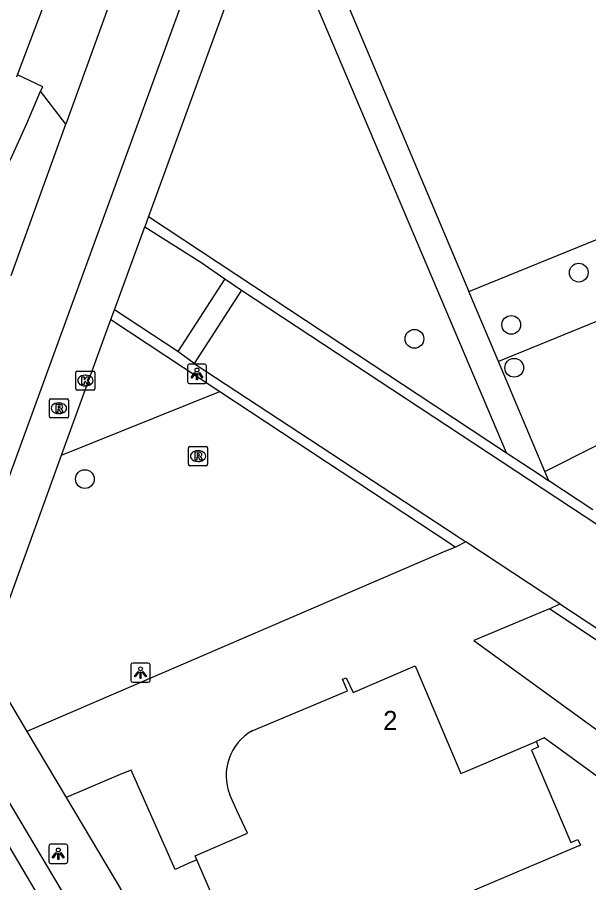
# Model space of a CAD drawing. Extents: x 156664 to 157568, y 383571 to 384421.
# Drawn here: x 156680.16 to 156709.98, y 383856.29 to 383901.43 of the extents above; entities that cross this region are included whole.
import ezdxf

# ---------------------------------------------------------------- set-up
doc = ezdxf.new("R2010")
doc.units = 0
for name, color, linetype in [('IMGEO_Boom', 7, 'Continuous'), ('IMGEO_Fietspad_open', 7, 'Continuous'), ('IMGEO_Groenvoorziening', 7, 'Continuous'), ('IMGEO_Kolk', 7, 'Continuous'), ('IMGEO_Lichtpunt', 7, 'Continuous'), ('IMGEO_OVBaan_gesloten', 7, 'Continuous'), ('IMGEO_Pand', 7, 'Continuous'), ('IMGEO_Pand_nummerreeks', 7, 'Continuous'), ('IMGEO_Rijbaan_lokaal_halfverhard', 7, 'Continuous'), ('IMGEO_Rijbaan_lokaal_open', 7, 'Continuous'), ('IMGEO_Rioolput', 7, 'Continuous'), ('IMGEO_Voetpad_open', 7, 'Continuous')]:
    doc.layers.add(name, color=color, linetype=linetype)

msp = doc.modelspace()

# ---------------------------------------------------------------- linework, layer by layer
at = {"layer": 'IMGEO_Boom'}
for centre in [(156709.463, 383888.111), (156705.943, 383885.387), (156700.888, 383884.658), (156706.096, 383883.15), (156683.69, 383877.346)]:
    msp.add_circle(centre, 0.489, dxfattribs=at)
at = {"layer": 'IMGEO_Fietspad_open'}
for points in [[(156833.031, 384293.583), (156831.476, 384295.664), (156797.885, 384202.753), (156781.915, 384158.669), (156778.633, 384149.604), (156765.945, 384114.759), (156745.635, 384058.756), (156737.507, 384036.302), (156716.373, 383978.18), (156709.217, 383958.49), (156701.659, 383937.694), (156690.408, 383906.735), (156677.045, 383870.138), (156675.34, 383865.46)], [(156685.19, 383902.73), (156682.699, 383895.852)]]:
    msp.add_lwpolyline(points, dxfattribs=at)
at = {"layer": 'IMGEO_Groenvoorziening'}
for points in [[(156703.732, 383887.135), (156723.792, 383895.282), (156723.972, 383894.805)], [(156707.702, 383877.745), (156721.247, 383884.56), (156720.319, 383889.614), (156705.282, 383883.469)], [(156682.477, 383878.585), (156690.731, 383881.92)]]:
    msp.add_lwpolyline(points, dxfattribs=at)
at = {"layer": 'IMGEO_Kolk'}
for p, q in [((156683.218, 383882.054), (156683.218, 383882.906)), ((156683.293, 383882.98), (156684.145, 383882.98)), ((156683.706, 383882.76), (156683.731, 383882.76)), ((156684.219, 383882.906), (156684.219, 383882.054)), ((156683.729, 383882.2), (156683.704, 383882.2)), ((156684.145, 383881.98), (156683.293, 383881.98))]:
    msp.add_line(p, q, dxfattribs=at)
for points in [[(156683.218, 383882.054), (156683.218, 383882.906)], [(156683.293, 383882.98), (156684.145, 383882.98)], [(156683.539, 383882.68), (156683.662, 383882.68), (156683.662, 383882.529), (156683.792, 383882.68), (156683.956, 383882.68), (156683.81, 383882.529), (156683.963, 383882.28), (156683.811, 383882.28), (156683.726, 383882.444), (156683.662, 383882.377), (156683.662, 383882.28), (156683.539, 383882.28), (156683.539, 383882.68)], [(156684.219, 383882.906), (156684.219, 383882.054)], [(156684.145, 383881.98), (156683.293, 383881.98)]]:
    msp.add_lwpolyline(points, dxfattribs=at)
for centre, start, end in [((156683.295, 383882.904), 91.552, 178.448), ((156683.295, 383882.904), 91.552, 178.448), ((156684.143, 383882.904), 1.552, 88.448), ((156684.143, 383882.904), 1.552, 88.448), ((156683.295, 383882.056), 181.552, 268.448), ((156683.295, 383882.056), 181.552, 268.448), ((156684.143, 383882.056), 271.552, 358.448), ((156684.143, 383882.056), 271.552, 358.448)]:
    msp.add_arc(centre, 0.0765, start, end, dxfattribs=at)
for centre, major_axis, ratio, start_param, end_param in [((156683.705, 383882.48), (-0.387, 0.002), 0.722429, 4.712389, 7.853982), ((156683.73, 383882.48), (-0.39, 0.002), 0.717154, 1.570796, 4.712389)]:
    msp.add_ellipse(centre, major_axis=major_axis, ratio=ratio, start_param=start_param, end_param=end_param, dxfattribs=at)
at = {"layer": 'IMGEO_Lichtpunt'}
for p, q in [((156689.044, 383883.235), (156689.044, 383882.428)), ((156689.044, 383883.235), (156689.044, 383882.428)), ((156689.946, 383883.33), (156689.138, 383883.33)), ((156689.946, 383883.33), (156689.138, 383883.33)), ((156690.04, 383882.428), (156690.04, 383883.235)), ((156690.04, 383882.428), (156690.04, 383883.235)), ((156689.138, 383882.334), (156689.946, 383882.334)), ((156689.138, 383882.334), (156689.946, 383882.334)), ((156686.996, 383867.746), (156686.188, 383867.746)), ((156686.996, 383867.746), (156686.188, 383867.746)), ((156686.094, 383867.651), (156686.094, 383866.844)), ((156686.094, 383867.651), (156686.094, 383866.844)), ((156687.09, 383866.844), (156687.09, 383867.651)), ((156687.09, 383866.844), (156687.09, 383867.651)), ((156686.188, 383866.75), (156686.996, 383866.75)), ((156686.188, 383866.75), (156686.996, 383866.75)), ((156681.804, 383858.205), (156681.804, 383857.398)), ((156681.804, 383858.205), (156681.804, 383857.398)), ((156682.706, 383858.3), (156681.898, 383858.3)), ((156682.706, 383858.3), (156681.898, 383858.3)), ((156682.8, 383857.398), (156682.8, 383858.205)), ((156682.8, 383857.398), (156682.8, 383858.205)), ((156681.898, 383857.304), (156682.706, 383857.304)), ((156681.898, 383857.304), (156682.706, 383857.304))]:
    msp.add_line(p, q, dxfattribs=at)
for points in [[(156689.418, 383882.899), (156689.457, 383882.871), (156689.269, 383882.609), (156689.231, 383882.636), (156689.418, 383882.899)], [(156689.52, 383882.851), (156689.567, 383882.851), (156689.567, 383882.529), (156689.52, 383882.529), (156689.52, 383882.851)], [(156689.63, 383882.871), (156689.668, 383882.898), (156689.855, 383882.636), (156689.816, 383882.608), (156689.63, 383882.871)], [(156686.468, 383867.315), (156686.507, 383867.287), (156686.319, 383867.025), (156686.281, 383867.052), (156686.468, 383867.315)], [(156686.57, 383867.267), (156686.617, 383867.267), (156686.617, 383866.945), (156686.57, 383866.945), (156686.57, 383867.267)], [(156686.68, 383867.287), (156686.718, 383867.314), (156686.905, 383867.052), (156686.866, 383867.024), (156686.68, 383867.287)], [(156682.178, 383857.869), (156682.217, 383857.841), (156682.029, 383857.579), (156681.991, 383857.606), (156682.178, 383857.869)], [(156682.28, 383857.821), (156682.327, 383857.821), (156682.327, 383857.499), (156682.28, 383857.499), (156682.28, 383857.821)], [(156682.39, 383857.841), (156682.428, 383857.868), (156682.615, 383857.606), (156682.576, 383857.578), (156682.39, 383857.841)]]:
    msp.add_lwpolyline(points, dxfattribs=at)
for centre in [(156689.543, 383883.033), (156686.593, 383867.449), (156682.303, 383858.003)]:
    msp.add_circle(centre, 0.0994, dxfattribs=at)
for centre, start, end in [((156689.138, 383883.235), 90, 180), ((156689.138, 383883.235), 90, 180), ((156689.946, 383883.235), 0, 90), ((156689.946, 383883.235), 0, 90), ((156689.138, 383882.428), 180, 270), ((156689.138, 383882.428), 180, 270), ((156689.946, 383882.428), 270, 0), ((156689.946, 383882.428), 270, 360), ((156686.188, 383867.651), 90, 180), ((156686.188, 383867.651), 90, 180), ((156686.996, 383867.651), 0, 90), ((156686.996, 383867.651), 0, 90), ((156686.188, 383866.844), 180, 270), ((156686.188, 383866.844), 180, 270), ((156686.996, 383866.844), 270, 0), ((156686.996, 383866.844), 270, 360), ((156681.898, 383858.205), 90, 180), ((156681.898, 383858.205), 90, 180), ((156682.706, 383858.205), 0, 90), ((156682.706, 383858.205), 0, 90), ((156681.898, 383857.398), 180, 270), ((156681.898, 383857.398), 180, 270), ((156682.706, 383857.398), 270, 0), ((156682.706, 383857.398), 270, 360)]:
    msp.add_arc(centre, 0.0946, start, end, dxfattribs=at)
at = {"layer": 'IMGEO_OVBaan_gesloten'}
msp.add_lwpolyline([(156692.043, 383837.395), (156678.244, 383860.711)], dxfattribs=at)
at = {"layer": 'IMGEO_Pand'}
for points in [[(156692.428, 383864.216), (156697.403, 383866.292), (156697.143, 383866.907), (156697.33, 383866.987), (156697.694, 383866.219), (156700.923, 383867.6), (156703.32, 383861.991), (156703.808, 383862.199), (156707.237, 383863.666)], [(156707.237, 383863.666), (156707.363, 383863.372), (156706.995, 383863.214), (156709.056, 383858.397), (156709.424, 383858.554), (156709.549, 383858.26), (156704.398, 383856.067), (156692.389, 383850.886), (156689.54, 383857.489)], [(156689.54, 383857.489), (156689.45, 383857.699), (156692.177, 383858.875), (156691.614, 383860.059), (156691.257, 383860.885)]]:
    msp.add_lwpolyline(points, dxfattribs=at)
msp.add_arc((156693.739, 383861.884), 2.676, 119.3437, 201.9185, dxfattribs=at)
at = {"layer": 'IMGEO_Rijbaan_lokaal_halfverhard'}
for points in [[(156687.008, 383891.046), (156686.812, 383890.508)], [(156687.008, 383891.046), (156697.05, 383884.421), (156701.09, 383881.756), (156705.692, 383878.72)], [(156685.05, 383885.669), (156685.231, 383886.168)], [(156685.05, 383885.669), (156690.731, 383881.92)], [(156690.731, 383881.92), (156702.732, 383874), (156703.031, 383873.802)], [(156705.692, 383878.72), (156707.4, 383877.593), (156707.907, 383877.258)], [(156710.197, 383875.747), (156707.907, 383877.258)], [(156703.578, 383874.065), (156703.031, 383873.802)], [(156707.93, 383870.575), (156708.48, 383870.841)], [(156724.088, 383859.825), (156708.317, 383870.317), (156707.93, 383870.575)]]:
    msp.add_lwpolyline(points, dxfattribs=at)
at = {"layer": 'IMGEO_Rijbaan_lokaal_open'}
for points in [[(156680.183, 383898.426), (156682.204, 383903.825)], [(156680.146, 383898.326), (156680.183, 383898.426)], [(156681.368, 383897.568), (156681.498, 383897.809), (156680.183, 383898.426)], [(156676.643, 383888.338), (156677.506, 383889.734), (156678.327, 383891.155), (156679.104, 383892.6), (156679.914, 383894.23), (156680.669, 383895.887), (156681.368, 383897.568)], [(156682.699, 383895.852), (156681.368, 383897.568)], [(156679.844, 383887.968), (156682.699, 383895.852)], [(156685.231, 383886.168), (156686.812, 383890.508)], [(156686.812, 383890.508), (156689.735, 383888.649), (156690.998, 383887.79)], [(156690.998, 383887.79), (156688.55, 383883.993)], [(156690.998, 383887.79), (156691.868, 383887.197)], [(156691.868, 383887.197), (156689.389, 383883.375)], [(156691.868, 383887.197), (156726.961, 383864.085)], [(156688.55, 383883.993), (156688.542, 383883.999), (156685.231, 383886.168)], [(156689.389, 383883.375), (156688.55, 383883.993)], [(156689.389, 383883.375), (156703.099, 383874.38), (156703.578, 383874.065)], [(156708.48, 383870.841), (156703.578, 383874.065)], [(156708.48, 383870.841), (156724.436, 383860.345)]]:
    msp.add_lwpolyline(points, dxfattribs=at)
at = {"layer": 'IMGEO_Rioolput'}
for p, q in [((156681.837, 383880.61), (156681.837, 383881.462)), ((156681.912, 383881.536), (156682.764, 383881.536)), ((156682.325, 383881.316), (156682.35, 383881.316)), ((156682.838, 383881.462), (156682.838, 383880.61)), ((156682.348, 383880.756), (156682.323, 383880.756)), ((156682.764, 383880.536), (156681.912, 383880.536)), ((156689.097, 383878.114), (156689.097, 383878.966)), ((156689.172, 383879.04), (156690.024, 383879.04)), ((156690.098, 383878.966), (156690.098, 383878.114)), ((156689.585, 383878.82), (156689.61, 383878.82)), ((156689.608, 383878.26), (156689.583, 383878.26)), ((156690.024, 383878.04), (156689.172, 383878.04))]:
    msp.add_line(p, q, dxfattribs=at)
for points in [[(156681.837, 383880.61), (156681.837, 383881.462)], [(156681.912, 383881.536), (156682.764, 383881.536)], [(156682.426, 383881.234), (156682.174, 383881.236), (156682.174, 383880.836)], [(156682.838, 383881.462), (156682.838, 383880.61)], [(156682.174, 383880.836), (156682.298, 383880.836), (156682.298, 383880.998), (156682.309, 383880.998)], [(156682.352, 383881.155), (156682.298, 383881.155), (156682.298, 383881.074)], [(156682.298, 383881.074), (156682.35, 383881.074)], [(156682.356, 383880.969), (156682.427, 383880.836), (156682.567, 383880.836), (156682.502, 383880.962)], [(156682.764, 383880.536), (156681.912, 383880.536)], [(156689.097, 383878.114), (156689.097, 383878.966)], [(156689.172, 383879.04), (156690.024, 383879.04)], [(156690.098, 383878.966), (156690.098, 383878.114)], [(156689.686, 383878.738), (156689.434, 383878.74), (156689.434, 383878.34)], [(156689.434, 383878.34), (156689.558, 383878.34), (156689.558, 383878.502), (156689.569, 383878.502)], [(156689.612, 383878.659), (156689.558, 383878.659), (156689.558, 383878.578)], [(156689.558, 383878.578), (156689.61, 383878.578)], [(156689.616, 383878.473), (156689.687, 383878.34), (156689.827, 383878.34), (156689.762, 383878.466)], [(156690.024, 383878.04), (156689.172, 383878.04)]]:
    msp.add_lwpolyline(points, dxfattribs=at)
for centre, radius, start, end in [((156681.914, 383881.46), 0.0765, 91.552, 178.448), ((156681.914, 383881.46), 0.0765, 91.552, 178.448), ((156682.425, 383881.124), 0.109, 350.3612, 89.416), ((156682.762, 383881.46), 0.0765, 1.552, 88.448), ((156682.762, 383881.46), 0.0765, 1.552, 88.448), ((156682.308, 383880.945), 0.0533, 26.0293, 88.6989), ((156682.334, 383881.263), 0.19, 274.7715, 282.9687), ((156682.358, 383881.059), 0.0964, 77.0061, 93.1865), ((156682.372, 383881.116), 0.0378, 276.6634, 79.6772), ((156682.423, 383881.124), 0.112, 277.5842, 350.9817), ((156682.407, 383880.909), 0.108, 29.5134, 73.7905), ((156681.914, 383880.612), 0.0765, 181.552, 268.448), ((156681.914, 383880.612), 0.0765, 181.552, 268.448), ((156682.762, 383880.612), 0.0765, 271.552, 358.448), ((156682.762, 383880.612), 0.0765, 271.552, 358.448), ((156689.174, 383878.964), 0.0765, 91.552, 178.448), ((156689.174, 383878.964), 0.0765, 91.552, 178.448), ((156690.022, 383878.964), 0.0765, 1.552, 88.448), ((156690.022, 383878.964), 0.0765, 1.552, 88.448), ((156689.568, 383878.449), 0.0533, 26.0293, 88.6989), ((156689.594, 383878.767), 0.19, 274.7715, 282.9687), ((156689.618, 383878.563), 0.0964, 77.0061, 93.1865), ((156689.632, 383878.62), 0.0378, 276.6634, 79.6772), ((156689.685, 383878.628), 0.109, 350.3612, 89.416), ((156689.683, 383878.628), 0.112, 277.5842, 350.9817), ((156689.667, 383878.413), 0.108, 29.5134, 73.7905), ((156689.174, 383878.116), 0.0765, 181.552, 268.448), ((156689.174, 383878.116), 0.0765, 181.552, 268.448), ((156690.022, 383878.116), 0.0765, 271.552, 358.448), ((156690.022, 383878.116), 0.0765, 271.552, 358.448)]:
    msp.add_arc(centre, radius, start, end, dxfattribs=at)
for centre, major_axis, ratio, start_param, end_param in [((156682.324, 383881.036), (-0.387, 0.002), 0.722429, 4.712389, 7.853982), ((156682.349, 383881.036), (-0.39, 0.002), 0.717154, 1.570796, 4.712389), ((156689.584, 383878.54), (-0.387, 0.002), 0.722429, 4.712389, 7.853982), ((156689.609, 383878.54), (-0.39, 0.002), 0.717154, 1.570796, 4.712389)]:
    msp.add_ellipse(centre, major_axis=major_axis, ratio=ratio, start_param=start_param, end_param=end_param, dxfattribs=at)
at = {"layer": 'IMGEO_Voetpad_open'}
for points in [[(156693.984, 383910.189), (156703.732, 383887.135)], [(156693.23, 383908.111), (156692.453, 383905.972), (156687.008, 383891.046)], [(156705.692, 383878.72), (156693.23, 383908.111)], [(156705.282, 383883.469), (156703.732, 383887.135)], [(156682.477, 383878.585), (156685.05, 383885.669)], [(156707.702, 383877.745), (156705.282, 383883.469)], [(156678.542, 383867.746), (156678.565, 383867.81), (156682.477, 383878.585)], [(156707.907, 383877.258), (156707.702, 383877.745)], [(156703.031, 383873.802), (156702.384, 383873.524), (156680.663, 383864.185)], [(156707.93, 383870.575), (156707.439, 383870.369), (156703.983, 383868.92), (156728.241, 383851.334)], [(156678.542, 383867.746), (156680.663, 383864.185)], [(156680.663, 383864.185), (156682.717, 383860.738)], [(156727.201, 383849.634), (156707.654, 383863.85), (156707.237, 383863.666)], [(156689.54, 383857.489), (156689.081, 383857.291), (156688.398, 383856.983), (156686.114, 383862.164), (156685.661, 383861.994), (156682.717, 383860.738)], [(156692.043, 383837.395), (156693.107, 383838.038), (156679.277, 383861.3), (156678.244, 383860.711)], [(156682.717, 383860.738), (156696.966, 383836.824)]]:
    msp.add_lwpolyline(points, dxfattribs=at)

# ---------------------------------------------------------------- texts
at = {"layer": 'IMGEO_Pand_nummerreeks'}
msp.add_text('2', height=1, dxfattribs=at).set_placement((156699.26, 383864.253))

doc.saveas('drawing.dxf')
